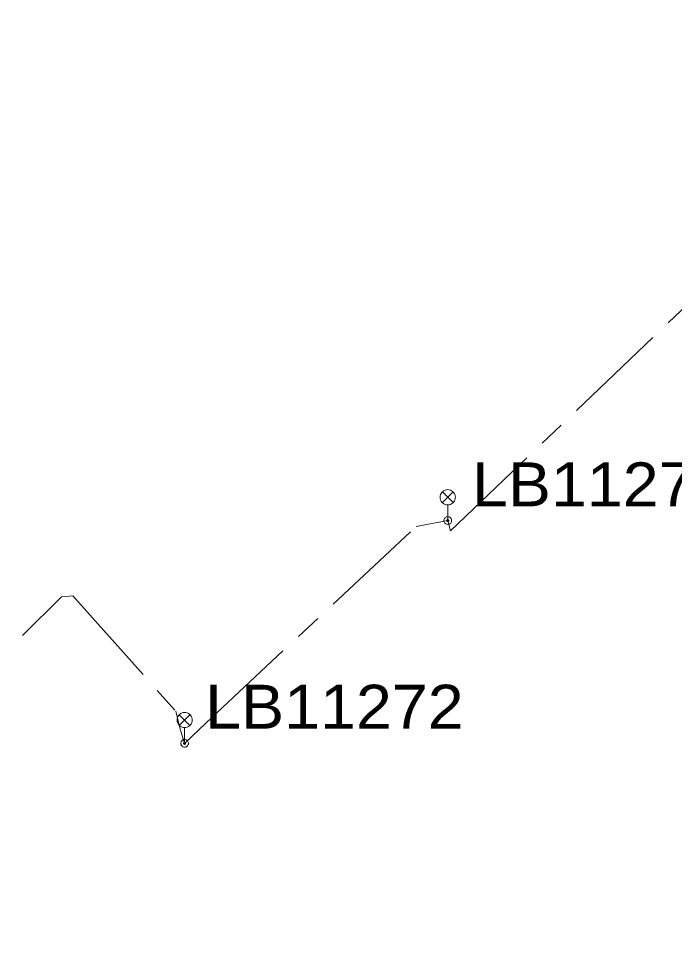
# Model space of a CAD drawing. Extents: x -688049 to -687261, y -973611 to -973038.
# Drawn here: x -687620.34 to -687587.95, y -973545.9 to -973499.85 of the extents above; entities that cross this region are included whole.
import ezdxf

# ---------------------------------------------------------------- set-up
doc = ezdxf.new("R2010")
doc.units = 0
doc.header["$LTSCALE"] = 0.87
doc.linetypes.add('LONG_DASH_SHORT_DASH', pattern=[9.9, 6, -1.2, 1.5, -1.2])
doc.layers.add('1', color=7, linetype='Continuous', lineweight=13)

msp = doc.modelspace()

# ---------------------------------------------------------------- linework, layer by layer
at = {"layer": '1'}
for p, q in [((-687599.405, -973523.215), (-687598.875, -973523.745)), ((-687599.405, -973523.745), (-687598.875, -973523.215)), ((-687599.14, -973524.63), (-687599.14, -973523.855)), ((-687612.405, -973534.215), (-687611.875, -973534.745)), ((-687612.405, -973534.745), (-687611.875, -973534.215)), ((-687612.14, -973535.63), (-687612.14, -973534.855))]:
    msp.add_line(p, q, dxfattribs=at)
at = {"layer": '1', "linetype": 'LONG_DASH_SHORT_DASH'}
for points in [[(-687599.14, -973524.63), (-687599.01, -973525.14), (-687586.17, -973512.89), (-687572.29, -973499.85)], [(-687599.14, -973524.63), (-687599.01, -973525.14), (-687586.17, -973512.89), (-687572.29, -973499.85)], [(-687599.14, -973524.63), (-687599.01, -973525.14), (-687586.17, -973512.89), (-687572.29, -973499.85)], [(-687599.14, -973524.63), (-687599.01, -973525.14), (-687586.17, -973512.89), (-687572.29, -973499.85)], [(-687599.14, -973524.63), (-687599.01, -973525.14), (-687586.17, -973512.89), (-687572.29, -973499.85)], [(-687599.14, -973524.63), (-687599.01, -973525.14), (-687586.17, -973512.89), (-687572.29, -973499.85)], [(-687599.14, -973524.63), (-687599.01, -973525.14), (-687586.17, -973512.89), (-687572.29, -973499.85)], [(-687599.14, -973524.63), (-687599.01, -973525.14), (-687586.17, -973512.89), (-687572.29, -973499.85)], [(-687612.14, -973535.63), (-687611.1, -973534.63), (-687600.7, -973524.93), (-687599.14, -973524.63)], [(-687612.14, -973535.63), (-687611.1, -973534.63), (-687600.7, -973524.93), (-687599.14, -973524.63)], [(-687612.14, -973535.63), (-687611.1, -973534.63), (-687600.7, -973524.93), (-687599.14, -973524.63)], [(-687612.14, -973535.63), (-687611.1, -973534.63), (-687600.7, -973524.93), (-687599.14, -973524.63)], [(-687612.14, -973535.63), (-687611.1, -973534.63), (-687600.7, -973524.93), (-687599.14, -973524.63)], [(-687612.14, -973535.63), (-687611.1, -973534.63), (-687600.7, -973524.93), (-687599.14, -973524.63)], [(-687612.14, -973535.63), (-687611.1, -973534.63), (-687600.7, -973524.93), (-687599.14, -973524.63)], [(-687612.14, -973535.63), (-687611.1, -973534.63), (-687600.7, -973524.93), (-687599.14, -973524.63)], [(-687636.02, -973545.9), (-687635.64, -973545.44), (-687634.29, -973542.81), (-687629.65, -973538.82), (-687628.33, -973538.35), (-687627.45, -973537.56), (-687626.27, -973536.36), (-687618.23, -973528.4), (-687617.66, -973528.34)], [(-687636.02, -973545.9), (-687635.64, -973545.44), (-687634.29, -973542.81), (-687629.65, -973538.82), (-687628.33, -973538.35), (-687627.45, -973537.56), (-687626.27, -973536.36), (-687618.23, -973528.4), (-687617.66, -973528.34)], [(-687636.02, -973545.9), (-687635.64, -973545.44), (-687634.29, -973542.81), (-687629.65, -973538.82), (-687628.33, -973538.35), (-687627.45, -973537.56), (-687626.27, -973536.36), (-687618.23, -973528.4), (-687617.66, -973528.34)], [(-687636.02, -973545.9), (-687635.64, -973545.44), (-687634.29, -973542.81), (-687629.65, -973538.82), (-687628.33, -973538.35), (-687627.45, -973537.56), (-687626.27, -973536.36), (-687618.23, -973528.4), (-687617.66, -973528.34)], [(-687636.02, -973545.9), (-687635.64, -973545.44), (-687634.29, -973542.81), (-687629.65, -973538.82), (-687628.33, -973538.35), (-687627.45, -973537.56), (-687626.27, -973536.36), (-687618.23, -973528.4), (-687617.66, -973528.34)], [(-687636.02, -973545.9), (-687635.64, -973545.44), (-687634.29, -973542.81), (-687629.65, -973538.82), (-687628.33, -973538.35), (-687627.45, -973537.56), (-687626.27, -973536.36), (-687618.23, -973528.4), (-687617.66, -973528.34)], [(-687636.02, -973545.9), (-687635.64, -973545.44), (-687634.29, -973542.81), (-687629.65, -973538.82), (-687628.33, -973538.35), (-687627.45, -973537.56), (-687626.27, -973536.36), (-687618.23, -973528.4), (-687617.66, -973528.34)], [(-687636.02, -973545.9), (-687635.64, -973545.44), (-687634.29, -973542.81), (-687629.65, -973538.82), (-687628.33, -973538.35), (-687627.45, -973537.56), (-687626.27, -973536.36), (-687618.23, -973528.4), (-687617.66, -973528.34)], [(-687617.66, -973528.34), (-687612.58, -973534.04), (-687612.38, -973534.86), (-687612.14, -973535.63)], [(-687617.66, -973528.34), (-687612.58, -973534.04), (-687612.38, -973534.86), (-687612.14, -973535.63)], [(-687617.66, -973528.34), (-687612.58, -973534.04), (-687612.38, -973534.86), (-687612.14, -973535.63)], [(-687617.66, -973528.34), (-687612.58, -973534.04), (-687612.38, -973534.86), (-687612.14, -973535.63)], [(-687617.66, -973528.34), (-687612.58, -973534.04), (-687612.38, -973534.86), (-687612.14, -973535.63)], [(-687617.66, -973528.34), (-687612.58, -973534.04), (-687612.38, -973534.86), (-687612.14, -973535.63)], [(-687617.66, -973528.34), (-687612.58, -973534.04), (-687612.38, -973534.86), (-687612.14, -973535.63)], [(-687617.66, -973528.34), (-687612.58, -973534.04), (-687612.38, -973534.86), (-687612.14, -973535.63)]]:
    msp.add_lwpolyline(points, dxfattribs=at)
at = {"layer": '1'}
for points in [[(-687598.765, -973523.48), (-687598.771, -973523.415), (-687598.788, -973523.352), (-687598.815, -973523.293), (-687598.853, -973523.239), (-687598.899, -973523.193), (-687598.952, -973523.155), (-687599.012, -973523.128), (-687599.075, -973523.111), (-687599.14, -973523.105), (-687599.205, -973523.111), (-687599.268, -973523.128), (-687599.328, -973523.155), (-687599.381, -973523.193), (-687599.427, -973523.239), (-687599.465, -973523.293), (-687599.492, -973523.352), (-687599.509, -973523.415), (-687599.515, -973523.48), (-687599.509, -973523.545), (-687599.492, -973523.608), (-687599.465, -973523.668), (-687599.427, -973523.721), (-687599.381, -973523.767), (-687599.328, -973523.805), (-687599.268, -973523.832), (-687599.205, -973523.849), (-687599.14, -973523.855), (-687599.075, -973523.849), (-687599.012, -973523.832), (-687598.952, -973523.805), (-687598.899, -973523.767), (-687598.853, -973523.721), (-687598.815, -973523.668), (-687598.788, -973523.608), (-687598.771, -973523.545)], [(-687598.95, -973524.63), (-687598.953, -973524.597), (-687598.961, -973524.565), (-687598.975, -973524.535), (-687598.994, -973524.508), (-687599.018, -973524.484), (-687599.045, -973524.465), (-687599.075, -973524.451), (-687599.107, -973524.443), (-687599.14, -973524.44), (-687599.173, -973524.443), (-687599.205, -973524.451), (-687599.235, -973524.465), (-687599.262, -973524.484), (-687599.286, -973524.508), (-687599.305, -973524.535), (-687599.319, -973524.565), (-687599.327, -973524.597), (-687599.33, -973524.63), (-687599.327, -973524.663), (-687599.319, -973524.695), (-687599.305, -973524.725), (-687599.286, -973524.752), (-687599.262, -973524.776), (-687599.235, -973524.795), (-687599.205, -973524.809), (-687599.173, -973524.817), (-687599.14, -973524.82), (-687599.107, -973524.817), (-687599.075, -973524.809), (-687599.045, -973524.795), (-687599.018, -973524.776), (-687598.994, -973524.752), (-687598.975, -973524.725), (-687598.961, -973524.695), (-687598.953, -973524.663)], [(-687599.09, -973524.63), (-687599.091, -973524.621), (-687599.093, -973524.613), (-687599.097, -973524.605), (-687599.102, -973524.598), (-687599.108, -973524.592), (-687599.115, -973524.587), (-687599.123, -973524.583), (-687599.131, -973524.581), (-687599.14, -973524.58), (-687599.149, -973524.581), (-687599.157, -973524.583), (-687599.165, -973524.587), (-687599.172, -973524.592), (-687599.178, -973524.598), (-687599.183, -973524.605), (-687599.187, -973524.613), (-687599.189, -973524.621), (-687599.19, -973524.63), (-687599.189, -973524.639), (-687599.187, -973524.647), (-687599.183, -973524.655), (-687599.178, -973524.662), (-687599.172, -973524.668), (-687599.165, -973524.673), (-687599.157, -973524.677), (-687599.149, -973524.679), (-687599.14, -973524.68), (-687599.131, -973524.679), (-687599.123, -973524.677), (-687599.115, -973524.673), (-687599.108, -973524.668), (-687599.102, -973524.662), (-687599.097, -973524.655), (-687599.093, -973524.647), (-687599.091, -973524.639)], [(-687611.765, -973534.48), (-687611.771, -973534.415), (-687611.788, -973534.352), (-687611.815, -973534.293), (-687611.853, -973534.239), (-687611.899, -973534.193), (-687611.952, -973534.155), (-687612.012, -973534.128), (-687612.075, -973534.111), (-687612.14, -973534.105), (-687612.205, -973534.111), (-687612.268, -973534.128), (-687612.328, -973534.155), (-687612.381, -973534.193), (-687612.427, -973534.239), (-687612.465, -973534.293), (-687612.492, -973534.352), (-687612.509, -973534.415), (-687612.515, -973534.48), (-687612.509, -973534.545), (-687612.492, -973534.608), (-687612.465, -973534.668), (-687612.427, -973534.721), (-687612.381, -973534.767), (-687612.328, -973534.805), (-687612.268, -973534.832), (-687612.205, -973534.849), (-687612.14, -973534.855), (-687612.075, -973534.849), (-687612.012, -973534.832), (-687611.952, -973534.805), (-687611.899, -973534.767), (-687611.853, -973534.721), (-687611.815, -973534.668), (-687611.788, -973534.608), (-687611.771, -973534.545)], [(-687611.95, -973535.63), (-687611.953, -973535.597), (-687611.961, -973535.565), (-687611.975, -973535.535), (-687611.994, -973535.508), (-687612.018, -973535.484), (-687612.045, -973535.465), (-687612.075, -973535.451), (-687612.107, -973535.443), (-687612.14, -973535.44), (-687612.173, -973535.443), (-687612.205, -973535.451), (-687612.235, -973535.465), (-687612.262, -973535.484), (-687612.286, -973535.508), (-687612.305, -973535.535), (-687612.319, -973535.565), (-687612.327, -973535.597), (-687612.33, -973535.63), (-687612.327, -973535.663), (-687612.319, -973535.695), (-687612.305, -973535.725), (-687612.286, -973535.752), (-687612.262, -973535.776), (-687612.235, -973535.795), (-687612.205, -973535.809), (-687612.173, -973535.817), (-687612.14, -973535.82), (-687612.107, -973535.817), (-687612.075, -973535.809), (-687612.045, -973535.795), (-687612.018, -973535.776), (-687611.994, -973535.752), (-687611.975, -973535.725), (-687611.961, -973535.695), (-687611.953, -973535.663)], [(-687612.09, -973535.63), (-687612.091, -973535.621), (-687612.093, -973535.613), (-687612.097, -973535.605), (-687612.102, -973535.598), (-687612.108, -973535.592), (-687612.115, -973535.587), (-687612.123, -973535.583), (-687612.131, -973535.581), (-687612.14, -973535.58), (-687612.149, -973535.581), (-687612.157, -973535.583), (-687612.165, -973535.587), (-687612.172, -973535.592), (-687612.178, -973535.598), (-687612.183, -973535.605), (-687612.187, -973535.613), (-687612.189, -973535.621), (-687612.19, -973535.63), (-687612.189, -973535.639), (-687612.187, -973535.647), (-687612.183, -973535.655), (-687612.178, -973535.662), (-687612.172, -973535.668), (-687612.165, -973535.673), (-687612.157, -973535.677), (-687612.149, -973535.679), (-687612.14, -973535.68), (-687612.131, -973535.679), (-687612.123, -973535.677), (-687612.115, -973535.673), (-687612.108, -973535.668), (-687612.102, -973535.662), (-687612.097, -973535.655), (-687612.093, -973535.647), (-687612.091, -973535.639)]]:
    msp.add_lwpolyline(points, close=True, dxfattribs=at)

# ---------------------------------------------------------------- texts
at = {"layer": '1', "width": 1.1}
for s, p in [('LB11273', (-687597.944, -973523.926)), ('LB11272', (-687611.124, -973534.905))]:
    msp.add_text(s, height=2.168, dxfattribs=at).set_placement(p)

doc.saveas('drawing.dxf')
